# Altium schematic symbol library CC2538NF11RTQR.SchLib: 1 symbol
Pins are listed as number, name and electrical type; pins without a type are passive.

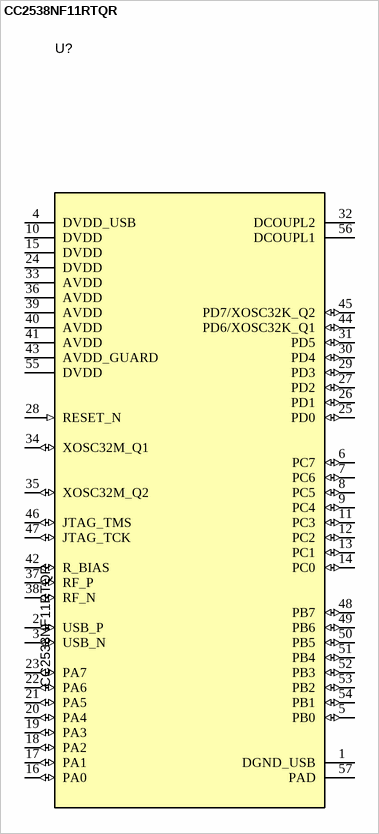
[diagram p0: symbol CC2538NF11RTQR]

## CC2538NF11RTQR
designator U?
A Powerful System-On-Chip for 2.4-GHz IEEE 802.15.4, 6LoWPAN and ZigBee Applications, RTQ0056F; Alternate PartNumber: CC2538NF11RTQT; Manufacturer: Texas Instruments; SymbolCreator: a0799628; SizeArea_mm2: 64; SizeAreaWB_mm2: 100; SizeX_mm: 8; SizeZ_mm: 1; CompType: IC; U/M: EA
footprint RTQ0056C
pins: 1 DGND_USB (power), 2 USB_P (io), 3 USB_N (io), 4 DVDD_USB (power), 5 PB0 (io), 6 PC7 (io), 7 PC6 (io), 8 PC5 (io), 9 PC4 (io), 10 DVDD (power), 11 PC3 (io), 12 PC2 (io), 13 PC1 (io), 14 PC0 (io), 15 DVDD (power), 16 PA0 (io), 17 PA1 (io), 18 PA2 (io), 19 PA3 (io), 20 PA4 (io), 21 PA5 (io), 22 PA6 (io), 23 PA7 (io), 24 DVDD (power), 25 PD0 (io), 26 PD1 (io), 27 PD2 (io), 28 RESET_N (in), 29 PD3 (io), 30 PD4 (io), 31 PD5 (io), 32 DCOUPL2, 33 AVDD (power), 34 XOSC32M_Q1 (io), 35 XOSC32M_Q2 (io), 36 AVDD (power), 37 RF_P (io), 38 RF_N (io), 39 AVDD (power), 40 AVDD (power), 41 AVDD (power), 42 R_BIAS (io), 43 AVDD_GUARD (power), 44 PD6/XOSC32K_Q1 (io), 45 PD7/XOSC32K_Q2 (io), 46 JTAG_TMS (io), 47 JTAG_TCK (io), 48 PB7 (io), 49 PB6 (io), 50 PB5 (io), 51 PB4 (io), 52 PB3 (io), 53 PB2 (io), 54 PB1 (io), 55 DVDD (power), 56 DCOUPL1 (power), 57 PAD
